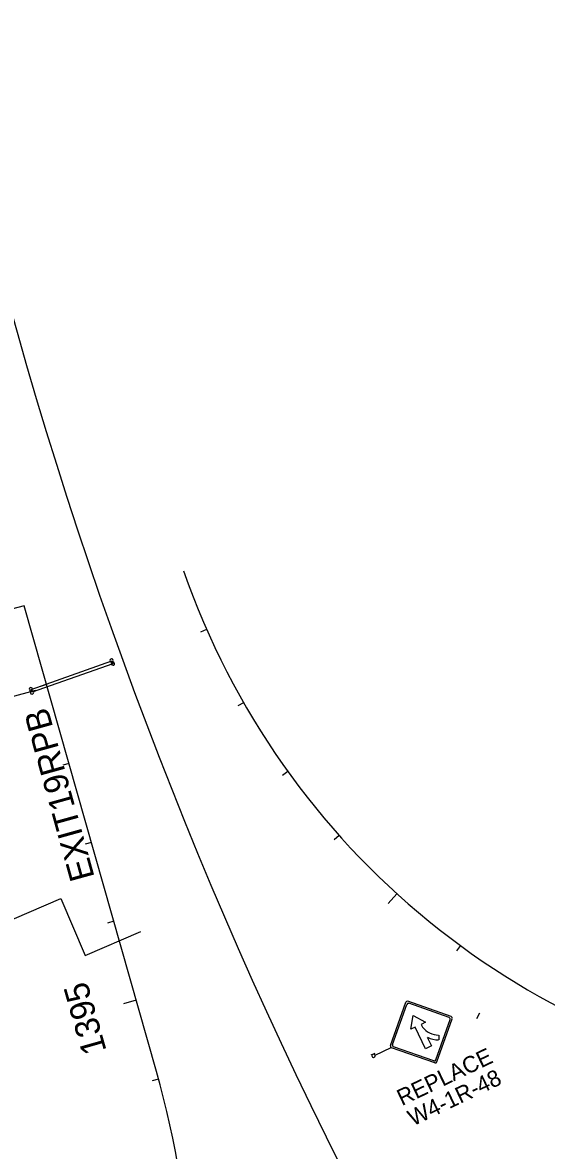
# Model space of a CAD drawing. Extents: x 2001876 to 2025694, y 804561 to 868938.
# Drawn here: x 2011665 to 2012304, y 825723 to 827099 of the extents above; entities that cross this region are included whole.
import ezdxf

# ---------------------------------------------------------------- set-up
doc = ezdxf.new("R2010")
doc.units = 0
for name, color, linetype in [('Default', 7, 'Continuous'), ('RD_EX_RW', 7, 'Continuous'), ('RD_EX_Sign', 7, 'Continuous'), ('RD_PD_CLEAR ZONE', 7, 'Continuous'), ('RD_PD_OHS', 7, 'Continuous'), ('RD_Sketch2', 7, 'Continuous'), ('RD_TX_RoadID', 7, 'Continuous'), ('TR SN EXTRUDED PANEL SIGNS - GROUND MOUNTED', 7, 'Continuous'), ('TR SN FLAT SHEET - TYPE III - FIXED SZ and MSG SIGN', 7, 'Continuous')]:
    doc.layers.add(name, color=color, linetype=linetype)

# ---------------------------------------------------------------- blocks, each defined once
blk = doc.blocks.new('SIGN2')
at = {"layer": 'Default'}
blk.add_lwpolyline([(-0.127, 0.169), (-0.127, -0.169)], dxfattribs=at)
for start, end in [(0, 180), (180, 0)]:
    blk.add_arc((0, 0), 0.127, start, end, dxfattribs=at)
blk = doc.blocks.new('OP')
at = {"layer": 'Default'}
for start, end in [(90, 270), (270, 90)]:
    blk.add_arc((0, 0), 0.127, start, end, dxfattribs=at)

msp = doc.modelspace()

# ---------------------------------------------------------------- linework, layer by layer
at = {"layer": 'RD_PD_CLEAR ZONE'}
msp.add_line((2011828.5, 825819.6), (2011667.2, 826387.6), dxfattribs=at)
for centre, radius, start, end in [((2017172.8, 828276.7), 5729.6, 180.6037, 207.5454), ((2012763.6, 826743.4), 954.9, 199.1498, 262.5361), ((2010726.1, 825506.6), 1145.9, 349.1442, 15.8524)]:
    msp.add_arc(centre, radius, start, end, dxfattribs=at)
at = {"layer": 'RD_PD_OHS'}
msp.add_lwpolyline([(2011775.4, 826316.8), (2011676.8, 826282), (2011675.5, 826285.4), (2011774.2, 826320.3)], close=True, dxfattribs=at)
at = {"layer": 'RD_Sketch2'}
for p, q in [((2011667.2, 826387.6), (2011651.8, 826383.2)), ((2011889.6, 826358.5), (2011882.3, 826355.3)), ((2011694.5, 826291.4), (2011686.8, 826289.2)), ((2011934.7, 826269.3), (2011927.7, 826265.3)), ((2011721.8, 826195.2), (2011714.1, 826193)), ((2011988.8, 826185.3), (2011982.3, 826180.6)), ((2012051.4, 826107.3), (2012045.4, 826102)), ((2011749.1, 826099), (2011741.4, 826096.8)), ((2012121.7, 826036.4), (2012111, 826024.5)), ((2011776.5, 826002.8), (2011768.8, 826000.6)), ((2012199.2, 825973.2), (2012194.4, 825966.7)), ((2011803.8, 825906.6), (2011788.4, 825902.2)), ((2012222.7, 825890.7), (2012218.7, 825883.8)), ((2011831, 825810.4), (2011823.3, 825808.3))]:
    msp.add_line(p, q, dxfattribs=at)
at = {"layer": 'TR SN EXTRUDED PANEL SIGNS - GROUND MOUNTED'}
for p, q in [((2011437, 826217.9), (2011681.5, 826284.7)), ((2011624.8, 825993.3), (2011711.8, 826030.5)), ((2011711.8, 826030.5), (2011741.5, 825961.1)), ((2011741.5, 825961.1), (2011809.4, 825990.2)), ((2012095.1, 825839.5), (2012114.7, 825848.9))]:
    msp.add_line(p, q, dxfattribs=at)
at = {"layer": 'TR SN FLAT SHEET - TYPE III - FIXED SZ and MSG SIGN'}
for p, q in [((2012114, 825851.2), (2012132.6, 825904)), ((2012116.5, 825852.4), (2012133.9, 825901.4)), ((2012188, 825886.6), (2012135.2, 825905.2)), ((2012185.4, 825885.3), (2012136.4, 825902.7)), ((2012138.8, 825871), (2012141.8, 825887.8)), ((2012141.8, 825887.8), (2012156.8, 825879.6)), ((2012169.3, 825833.8), (2012186.7, 825882.8)), ((2012170.6, 825831.2), (2012189.2, 825884)), ((2012144.2, 825873.6), (2012138.8, 825871)), ((2012156.7, 825847.4), (2012144.2, 825873.6)), ((2012156.8, 825879.6), (2012151.4, 825877)), ((2012151.4, 825877), (2012153, 825873.7)), ((2012158.9, 825861.3), (2012163.9, 825850.8)), ((2012172.8, 825864), (2012172.8, 825858)), ((2012168, 825830), (2012115.2, 825848.6)), ((2012166.8, 825832.5), (2012117.8, 825849.8)), ((2012163.9, 825850.8), (2012156.7, 825847.4))]:
    msp.add_line(p, q, dxfattribs=at)
for centre, radius, start, end in [((2012134.5, 825903.3), 2, 70.5573, 160.5564), ((2012135.7, 825900.8), 2, 70.5578, 160.5564), ((2012184.8, 825883.5), 2, 340.5564, 70.5542), ((2012187.3, 825884.7), 2, 340.5564, 70.5521), ((2012172.8, 825889.1), 25.1, 217.9045, 269.8376), ((2012172.8, 825889.1), 31.1, 243.4921, 269.8376), ((2012115.9, 825850.5), 2, 160.5564, 250.5572), ((2012118.4, 825851.7), 2, 160.5564, 250.5593), ((2012167.5, 825834.4), 2, 250.5548, 340.5548), ((2012168.7, 825831.9), 2, 250.5564, 340.5564)]:
    msp.add_arc(centre, radius, start, end, dxfattribs=at)

# ---------------------------------------------------------------- block references
at = {"layer": 'RD_EX_Sign', "xscale": 15.748031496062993, "yscale": 15.748031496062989, "rotation": -64.33994689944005}
msp.add_blockref('SIGN2', (2012093.3, 825838.7), dxfattribs=at)
at = {"layer": 'RD_PD_OHS', "xscale": 15.748031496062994, "yscale": 15.748031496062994, "rotation": 4.100579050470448}
for p in [(2011773.6, 826320.8), (2011775.4, 826316.9), (2011675.2, 826285.8), (2011676.7, 826281.6)]:
    msp.add_blockref('OP', p, dxfattribs=at)

# ---------------------------------------------------------------- texts
at = {"layer": 'RD_EX_RW'}
msp.add_text('1395', height=30, rotation=105.8524, dxfattribs=at).set_placement((2011767.8, 825845))
at = {"layer": 'RD_TX_RoadID'}
msp.add_text('EXIT19RPB', height=30, rotation=105.4808, dxfattribs=at).set_placement((2011753.2, 826056.6))
at = {"layer": 'TR SN EXTRUDED PANEL SIGNS - GROUND MOUNTED'}
for s, p in [('REPLACE', (2012127.9, 825777.3)), ('W4-1R-48', (2012141.3, 825752.5))]:
    msp.add_text(s, height=20, rotation=25.5309, dxfattribs=at).set_placement(p)

doc.saveas('drawing.dxf')
